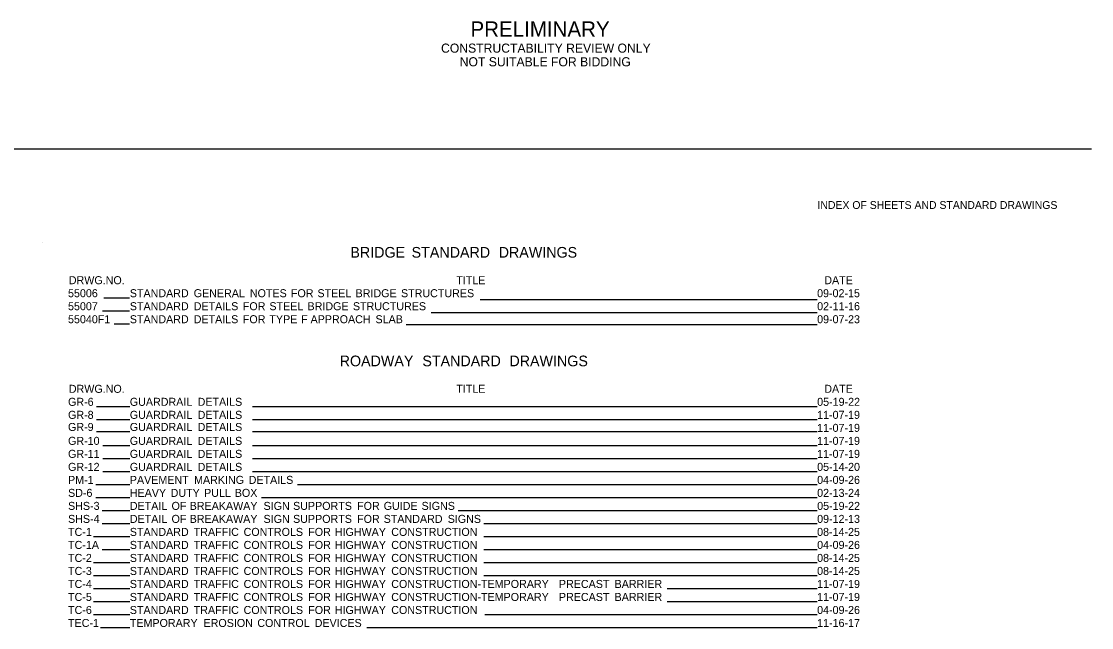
# Model space of a CAD drawing. Extents: x 76 to 3247, y 35 to 1167.
# Drawn here: x 869 to 1671, y 712 to 1167 of the extents above; entities that cross this region are included whole.
import ezdxf

# ---------------------------------------------------------------- set-up
doc = ezdxf.new("R2010")
doc.units = 0
for name, color, linetype in [('Default', 7, 'Continuous'), ('R_Border', 7, 'Continuous'), ('R_Draft', 7, 'Continuous')]:
    doc.layers.add(name, color=color, linetype=linetype)

msp = doc.modelspace()

# ---------------------------------------------------------------- linework, layer by layer
at = {"layer": 'Default'}
for p, q in [((75.8, 1071.16), (1671.16, 1071.16)), ((884.78, 1001.21), (884.78, 1001.21)), ((930.62, 959.55), (949.78, 959.55)), ((1212.67, 958.31), (1465.37, 958.31)), ((929.7, 949.8), (949.78, 949.8)), ((1176.09, 948.56), (1465.37, 948.56)), ((938.32, 940.05), (949.78, 940.05)), ((1157.19, 939.49), (1465.37, 939.49)), ((925.22, 878.12), (950.11, 878.12)), ((1042.09, 878.12), (1465.37, 878.12)), ((925.22, 868.37), (950.11, 868.37)), ((1042.09, 868.37), (1465.37, 868.37)), ((925.22, 859.3), (950.11, 859.3)), ((1042.09, 859.3), (1465.37, 859.3)), ((929.93, 848.87), (950.11, 848.87)), ((1042.09, 848.87), (1465.37, 848.87)), ((929.93, 839.12), (950.11, 839.12)), ((1042.09, 839.12), (1465.37, 839.12)), ((929.93, 829.37), (950.11, 829.37)), ((1042.09, 829.37), (1465.37, 829.37)), ((924.57, 819.62), (950.11, 819.62)), ((1075.8, 819.62), (1465.37, 819.62)), ((924.57, 809.87), (950.11, 809.87)), ((1048.79, 809.87), (1465.37, 809.87)), ((929.31, 800.12), (950.11, 800.12)), ((1196.22, 800.12), (1465.37, 800.12)), ((929.31, 790.37), (950.11, 790.37)), ((1215.4, 790.37), (1465.37, 790.37)), ((922.87, 780.62), (950.11, 780.62)), ((1215.4, 780.62), (1465.37, 780.62)), ((929.31, 770.87), (950.11, 770.87)), ((1215.4, 770.87), (1465.37, 770.87)), ((922.87, 761.12), (950.11, 761.12)), ((1215.4, 761.12), (1465.37, 761.12)), ((922.87, 751.37), (950.11, 751.37)), ((1215.4, 751.37), (1465.37, 751.37)), ((922.87, 741.62), (950.11, 741.62)), ((1352.98, 741.62), (1465.37, 741.62)), ((922.87, 731.87), (950.11, 731.87)), ((1352.98, 731.87), (1465.37, 731.87)), ((922.87, 722.12), (950.11, 722.12)), ((1216.22, 722.12), (1465.37, 722.12)), ((928.14, 712.37), (950.11, 712.37)), ((1127.8, 712.37), (1465.37, 712.37))]:
    msp.add_line(p, q, dxfattribs=at)

# ---------------------------------------------------------------- texts
for s, height, p in [('BRIDGE', 8, (1115.48, 989.65)), (' STANDARD', 8, (1158.4, 989.65)), (' DRAWINGS', 8, (1223.67, 989.65)), ('DRWG.NO.', 6, (904.38, 969.75)), ('TITLE', 6, (1194.85, 969.75)), ('DATE', 6, (1470.76, 969.75)), ('55006', 6, (903.79, 960)), ('STANDARD', 6, (950.11, 960)), (' GENERAL', 6, (995.78, 960)), (' NOTES', 6, (1037.88, 960)), (' FOR', 6, (1068.65, 960)), (' STEEL', 6, (1088.56, 960)), (' BRIDGE', 6, (1117.15, 960)), (' STRUCTURES', 6, (1151.18, 960)), ('09-02-15', 6, (1465.37, 960)), ('55007', 6, (903.79, 950.25)), ('STANDARD', 6, (950.11, 950.25)), (' DETAILS', 6, (995.78, 950.25)), (' FOR', 6, (1032.61, 950.25)), (' STEEL', 6, (1052.52, 950.25)), (' BRIDGE', 6, (1081.11, 950.25)), (' STRUCTURES', 6, (1115.14, 950.25)), ('02-11-16', 6, (1465.39, 950.25)), ('55040F1', 6, (903.79, 940.5)), ('STANDARD', 6, (950.11, 940.5)), (' DETAILS', 6, (995.78, 940.5)), (' FOR', 6, (1032.61, 940.5)), (' TYPE', 6, (1052.52, 940.5)), (' F', 6, (1076.3, 940.5)), (' APPROACH', 6, (1083.37, 940.5)), (' SLAB', 6, (1132.08, 940.5)), ('09-07-23', 6, (1465.39, 940.5)), ('ROADWAY', 8, (1107.43, 908.24)), (' STANDARD', 8, (1166.44, 908.24)), (' DRAWINGS', 8, (1231.72, 908.24)), ('DRWG.NO.', 6, (904.38, 888.34)), ('TITLE', 6, (1194.85, 888.34)), ('DATE', 6, (1470.76, 888.34)), ('GR-6', 6, (903.79, 878.59)), ('GUARDRAIL', 6, (950.11, 878.59)), (' DETAILS', 6, (998.72, 878.59)), ('05-19-22', 6, (1465.42, 878.59)), ('GR-8', 6, (903.79, 868.84)), ('GUARDRAIL', 6, (950.11, 868.84)), (' DETAILS', 6, (998.72, 868.84)), ('11-07-19', 6, (1465.38, 868.84)), ('GR-9', 6, (903.79, 859.76)), ('GUARDRAIL', 6, (950.11, 859.76)), (' DETAILS', 6, (998.72, 859.76)), ('11-07-19', 6, (1465.38, 859.09)), ('GR-10', 6, (903.79, 849.34)), ('GUARDRAIL', 6, (950.11, 849.34)), (' DETAILS', 6, (998.72, 849.34)), ('11-07-19', 6, (1465.38, 849.34)), ('GR-11', 6, (903.79, 839.59)), ('GUARDRAIL', 6, (950.11, 839.59)), (' DETAILS', 6, (998.72, 839.59)), ('11-07-19', 6, (1465.38, 839.59)), ('GR-12', 6, (903.79, 829.84)), ('GUARDRAIL', 6, (950.11, 829.84)), (' DETAILS', 6, (998.72, 829.84)), ('05-14-20', 6, (1465.4, 829.84)), ('PM-1', 6, (903.79, 820.09)), ('PAVEMENT', 6, (950.11, 820.09)), (' MARKING', 6, (996.06, 820.09)), (' DETAILS', 6, (1036.99, 820.09)), ('04-09-26', 6, (1465.39, 820.09)), ('SD-6', 6, (903.79, 810.34)), ('HEAVY', 6, (950.11, 810.34)), (' DUTY', 6, (978.47, 810.34)), (' PULL', 6, (1003.56, 810.34)), (' BOX', 6, (1026.56, 810.34)), ('02-13-24', 6, (1465.4, 810.34)), ('SHS-3', 6, (903.79, 800.59)), ('DETAIL', 6, (950.11, 800.59)), (' OF', 6, (979.16, 800.59)), (' BREAKAWAY', 6, (992.75, 800.59)), (' SIGN', 6, (1048.13, 800.59)), (' SUPPORTS', 6, (1070.27, 800.59)), (' FOR', 6, (1118.28, 800.59)), (' GUIDE', 6, (1138.19, 800.59)), (' SIGNS', 6, (1166.62, 800.59)), ('05-19-22', 6, (1465.42, 800.59)), ('SHS-4', 6, (903.79, 790.84)), ('DETAIL', 6, (950.11, 790.84)), (' OF', 6, (979.16, 790.84)), (' BREAKAWAY', 6, (992.75, 790.84)), (' SIGN', 6, (1048.13, 790.84)), (' SUPPORTS', 6, (1070.27, 790.84)), (' FOR', 6, (1118.28, 790.84)), (' STANDARD', 6, (1138.19, 790.84)), (' SIGNS', 6, (1186.19, 790.84)), ('09-12-13', 6, (1465.39, 790.84)), ('TC-1', 6, (903.79, 781.09)), ('STANDARD', 6, (950.11, 781.09)), (' TRAFFIC', 6, (995.78, 781.09)), (' CONTROLS', 6, (1033.17, 781.09)), (' FOR', 6, (1081.64, 781.09)), (' HIGHWAY', 6, (1101.55, 781.09)), (' CONSTRUCTION', 6, (1143.87, 781.09)), ('08-14-25', 6, (1465.37, 781.09)), ('TC-1A', 6, (903.79, 771.34)), ('STANDARD', 6, (950.11, 771.34)), (' TRAFFIC', 6, (995.78, 771.34)), (' CONTROLS', 6, (1033.17, 771.34)), (' FOR', 6, (1081.64, 771.34)), (' HIGHWAY', 6, (1101.55, 771.34)), (' CONSTRUCTION', 6, (1143.87, 771.34)), ('04-09-26', 6, (1465.39, 771.34)), ('TC-2', 6, (903.79, 761.59)), ('STANDARD', 6, (950.11, 761.59)), (' TRAFFIC', 6, (995.78, 761.59)), (' CONTROLS', 6, (1033.17, 761.59)), (' FOR', 6, (1081.64, 761.59)), (' HIGHWAY', 6, (1101.55, 761.59)), (' CONSTRUCTION', 6, (1143.87, 761.59)), ('08-14-25', 6, (1465.37, 761.59)), ('TC-3', 6, (903.79, 751.84)), ('STANDARD', 6, (950.11, 751.84)), (' TRAFFIC', 6, (995.78, 751.84)), (' CONTROLS', 6, (1033.17, 751.84)), (' FOR', 6, (1081.64, 751.84)), (' HIGHWAY', 6, (1101.55, 751.84)), (' CONSTRUCTION', 6, (1143.87, 751.84)), ('08-14-25', 6, (1465.37, 751.84)), ('TC-4', 6, (903.79, 742.09)), ('STANDARD', 6, (950.11, 742.09)), (' TRAFFIC', 6, (995.78, 742.09)), (' CONTROLS', 6, (1033.17, 742.09)), (' FOR', 6, (1081.64, 742.09)), (' HIGHWAY', 6, (1101.55, 742.09)), (' CONSTRUCTION-TEMPORARY', 6, (1143.87, 742.09)), (' PRECAST', 6, (1269.57, 742.09)), (' BARRIER', 6, (1311.33, 742.09)), ('11-07-19', 6, (1465.38, 742.09)), ('TC-5', 6, (903.79, 732.34)), ('STANDARD', 6, (950.11, 732.34)), (' TRAFFIC', 6, (995.78, 732.34)), (' CONTROLS', 6, (1033.17, 732.34)), (' FOR', 6, (1081.64, 732.34)), (' HIGHWAY', 6, (1101.55, 732.34)), (' CONSTRUCTION-TEMPORARY', 6, (1143.87, 732.34)), (' PRECAST', 6, (1269.57, 732.34)), (' BARRIER', 6, (1311.33, 732.34)), ('11-07-19', 6, (1465.38, 732.34)), ('TC-6', 6, (903.79, 722.59)), ('STANDARD', 6, (950.11, 722.59)), (' TRAFFIC', 6, (995.78, 722.59)), (' CONTROLS', 6, (1033.17, 722.59)), (' FOR', 6, (1081.64, 722.59)), (' HIGHWAY', 6, (1101.55, 722.59)), (' CONSTRUCTION', 6, (1143.87, 722.59)), ('04-09-26', 6, (1465.39, 722.59)), ('TEC-1', 6, (903.79, 712.84)), ('TEMPORARY', 6, (950.11, 712.84)), (' EROSION', 6, (1003.15, 712.84)), (' CONTROL', 6, (1043.46, 712.84)), (' DEVICES', 6, (1086.48, 712.84)), ('11-16-17', 6, (1465.39, 712.84))]:
    msp.add_text(s, height=height, dxfattribs=at).set_placement(p)
at = {"layer": 'R_Border'}
msp.add_text('INDEX OF SHEETS AND STANDARD DRAWINGS', height=5.862, dxfattribs=at).set_placement((1465.64, 1026.18))
at = {"layer": 'R_Draft'}
for s, height, p in [('PRELIMINARY', 11.508, (1205.51, 1155.22)), ('CONSTRUCTABILITY REVIEW ONLY', 6.823, (1183.44, 1143.28)), ('NOT SUITABLE FOR BIDDING', 6.823, (1197.43, 1133.05))]:
    msp.add_text(s, height=height, rotation=0.00001, dxfattribs=at).set_placement(p)

doc.saveas('drawing.dxf')
